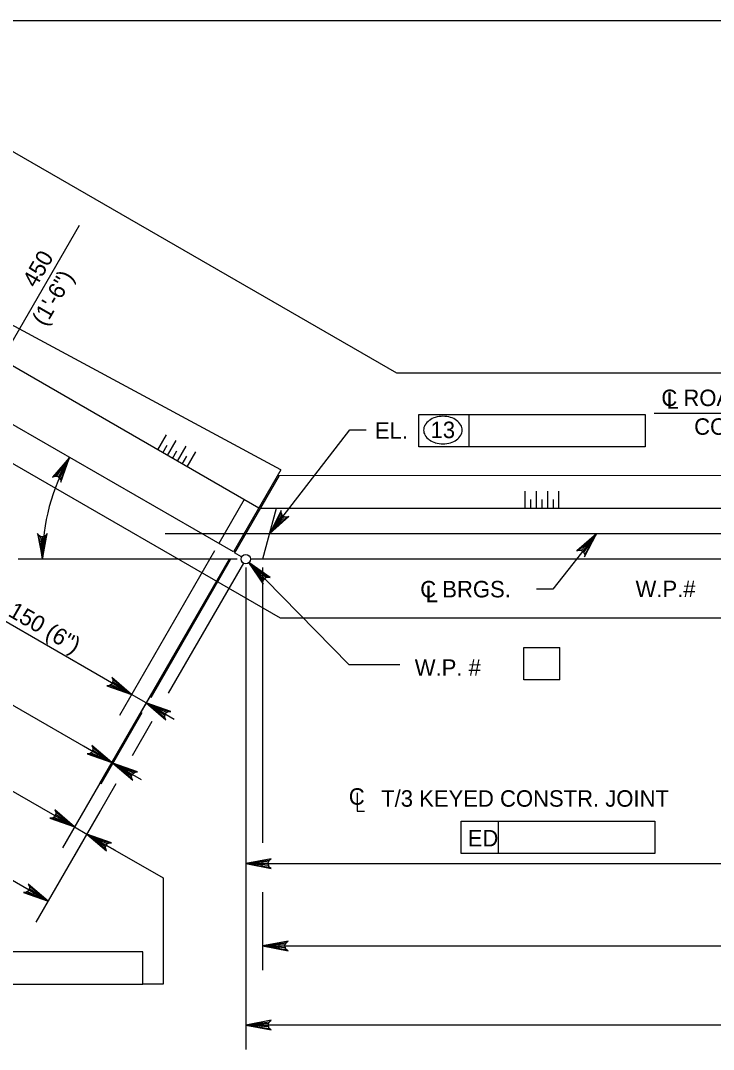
# Model space of a CAD drawing. Extents: x 638340 to 640241, y 295465 to 298435.
# Drawn here: x 638568.5 to 638694.6, y 297045.1 to 297232.5 of the extents above; entities that cross this region are included whole.
import ezdxf

# ---------------------------------------------------------------- set-up
doc = ezdxf.new("R2010")
doc.units = 0
for name, color, linetype in [('10', 7, 'Continuous'), ('2', 7, 'Continuous'), ('3', 7, 'Continuous')]:
    doc.layers.add(name, color=color, linetype=linetype)

msp = doc.modelspace()

# ---------------------------------------------------------------- linework, layer by layer
at = {"layer": '10'}
for p, q in [((638636.98, 297168.22), (638562.15, 297211.42)), ((638615.83, 297150.61), (638548.15, 297187.17)), ((638611.82, 297143.67), (638545.23, 297182.12)), ((638607.21, 297135.68), (638541.35, 297173.7)), ((638615.8, 297123.61), (638537.54, 297168.8)), ((638811.23, 297168.22), (638636.98, 297168.22)), ((638615.83, 297150.61), (638607.21, 297135.68)), ((638615.56, 297149.63), (638607.43, 297135.55)), ((638615.56, 297149.63), (638831.73, 297149.7)), ((638609.16, 297145.21), (638604.55, 297137.22)), ((638835.25, 297143.61), (638612.08, 297143.61)), ((638615.01, 297143.61), (638612.53, 297134.38)), ((638860.01, 297138.99), (638594.8, 297138.99)), ((638608.72, 297134.81), (638607.43, 297135.55)), ((638725.26, 297134.38), (638610.31, 297134.38)), ((638835.48, 297123.61), (638615.8, 297123.61))]:
    msp.add_line(p, q, dxfattribs=at)
at = {"layer": '2'}
for p, q in [((638475.46, 297232.46), (639261.46, 297232.46)), ((638593.47, 297154.26), (638595.05, 297157)), ((638594.36, 297153.75), (638595.17, 297155.16)), ((638595.25, 297153.24), (638596.83, 297155.98)), ((638597.02, 297152.21), (638598.6, 297154.95)), ((638596.13, 297152.73), (638596.95, 297154.13)), ((638597.91, 297151.7), (638598.72, 297153.11)), ((638598.8, 297151.19), (638600.38, 297153.93)), ((638660.33, 297143.61), (638660.33, 297146.77)), ((638661.36, 297143.61), (638661.36, 297145.23)), ((638662.38, 297143.61), (638662.38, 297146.77)), ((638663.41, 297143.61), (638663.41, 297145.23)), ((638664.43, 297143.61), (638664.43, 297146.77)), ((638665.46, 297143.61), (638665.46, 297145.23)), ((638666.48, 297143.61), (638666.48, 297146.77))]:
    msp.add_line(p, q, dxfattribs=at)
at = {"layer": '3'}
for p, q in [((638566.54, 297173.23), (638579.21, 297195.19)), ((638640.98, 297160.72), (638650.16, 297160.72)), ((638640.98, 297154.82), (638640.98, 297160.72)), ((638650.16, 297154.82), (638650.16, 297160.72)), ((638650.16, 297160.72), (638682.2, 297160.72)), ((638682.2, 297160.72), (638682.2, 297154.82)), ((638718.45, 297160.92), (638683.82, 297160.92)), ((638613.77, 297138.99), (638628.44, 297157.93)), ((638628.44, 297157.93), (638631.4, 297157.93)), ((638682.2, 297154.82), (638640.98, 297154.82)), ((638673.33, 297138.99), (638665.37, 297128.91)), ((638603.78, 297135.88), (638586.47, 297105.91)), ((638607.92, 297134.38), (638568.02, 297134.38)), ((638606.44, 297134.35), (638576.09, 297081.78)), ((638606.44, 297134.35), (638582.86, 297093.5)), ((638606.44, 297134.35), (638589.13, 297104.37)), ((638606.66, 297134.22), (638592.17, 297109.12)), ((638585.07, 297097.33), (638524.29, 297132.45)), ((638609.03, 297133.64), (638595.36, 297109.95)), ((638609.46, 297132.84), (638609.46, 297074.5)), ((638610.02, 297133.74), (638628.24, 297115.21)), ((638612.53, 297132.84), (638612.53, 297082.7)), ((638665.37, 297128.91), (638662.41, 297128.91)), ((638583.57, 297112.7), (638561.85, 297125.23)), ((638511.71, 297124.06), (638578.3, 297085.61)), ((638660.06, 297118.29), (638666.66, 297118.29)), ((638660.06, 297112.38), (638660.06, 297118.29)), ((638666.66, 297112.38), (638666.66, 297118.29)), ((638628.24, 297115.21), (638637.49, 297115.21)), ((638573.49, 297072.08), (638504.64, 297111.82)), ((638588.68, 297109.74), (638583.57, 297112.7)), ((638666.66, 297112.38), (638660.06, 297112.38)), ((638591.35, 297108.21), (638588.69, 297109.75)), ((638591.35, 297108.21), (638596.46, 297105.25)), ((638590.58, 297106.37), (638583.08, 297093.37)), ((638592.37, 297104.79), (638588.77, 297098.55)), ((638582.52, 297098.81), (638579.96, 297100.29)), ((638585.29, 297097.21), (638585.07, 297097.34)), ((638585.29, 297097.21), (638590.41, 297094.25)), ((638585.84, 297093.48), (638578.34, 297080.48)), ((638609.46, 297093.82), (638609.46, 297045.09)), ((638629.72, 297091.82), (638629.72, 297088.5)), ((638582.91, 297088.39), (638571.27, 297068.24)), ((638575.75, 297087.09), (638573.19, 297088.56)), ((638629.72, 297088.5), (638631.11, 297088.5)), ((638578.3, 297085.61), (638580.55, 297084.31)), ((638648.66, 297086.66), (638655.5, 297086.66)), ((638648.66, 297080.75), (638648.66, 297086.66)), ((638655.5, 297080.75), (638655.5, 297086.66)), ((638655.5, 297086.66), (638683.96, 297086.66)), ((638683.96, 297086.66), (638683.96, 297080.75)), ((638580.55, 297084.32), (638594.42, 297076.31)), ((638583.11, 297082.84), (638585.67, 297081.36)), ((638683.96, 297080.75), (638648.66, 297080.75)), ((638609.46, 297078.93), (638718.12, 297078.93)), ((638594.42, 297076.31), (638594.42, 297056.96)), ((638612.53, 297073.71), (638612.53, 297059.5)), ((638583.87, 297062.86), (638555.41, 297062.86)), ((638590.71, 297062.86), (638583.87, 297062.86)), ((638590.71, 297056.96), (638590.71, 297062.86)), ((638612.53, 297063.93), (638829.61, 297063.93)), ((638555.41, 297056.96), (638590.71, 297056.96)), ((638594.42, 297056.96), (638590.71, 297056.96)), ((638837.73, 297049.52), (638609.46, 297049.52))]:
    msp.add_line(p, q, dxfattribs=at)
for points in [[(638577.4, 297152.89), (638574.32, 297149.29), (638574.71, 297149.47), (638575.08, 297149.48), (638575.37, 297149.37), (638575.62, 297149.16), (638575.8, 297148.85), (638575.83, 297148.41), (638577.4, 297152.89), (638575.8, 297148.85), (638575.62, 297149.16), (638577.4, 297152.89), (638575.37, 297149.37), (638575.08, 297149.48), (638577.4, 297152.89), (638574.71, 297149.47)], [(638613.77, 297138.99), (638617.32, 297142.14), (638616.9, 297142.01), (638616.54, 297142.06), (638616.26, 297142.2), (638616.04, 297142.44), (638615.91, 297142.78), (638615.93, 297143.21), (638613.77, 297138.99), (638615.91, 297142.78), (638616.04, 297142.44), (638613.77, 297138.99), (638616.26, 297142.2), (638616.54, 297142.06), (638613.77, 297138.99), (638616.9, 297142.01)], [(638572.45, 297134.38), (638573.32, 297139.04), (638573.07, 297138.68), (638572.76, 297138.5), (638572.45, 297138.44), (638572.13, 297138.5), (638571.82, 297138.68), (638571.57, 297139.04), (638572.45, 297134.38), (638571.82, 297138.68), (638572.13, 297138.5), (638572.45, 297134.38), (638572.45, 297138.44), (638572.76, 297138.5), (638572.45, 297134.38), (638573.07, 297138.68)], [(638673.33, 297138.99), (638669.76, 297135.88), (638670.18, 297136.01), (638670.54, 297135.96), (638670.82, 297135.81), (638671.03, 297135.57), (638671.16, 297135.23), (638671.13, 297134.8), (638673.33, 297138.99), (638671.16, 297135.23), (638671.03, 297135.57), (638673.33, 297138.99), (638670.82, 297135.81), (638670.54, 297135.96), (638673.33, 297138.99), (638670.18, 297136.01)], [(638610.02, 297133.74), (638612.66, 297129.81), (638612.59, 297130.24), (638612.68, 297130.59), (638612.87, 297130.85), (638613.13, 297131.03), (638613.48, 297131.11), (638613.91, 297131.03), (638610.02, 297133.74), (638613.48, 297131.11), (638613.13, 297131.03), (638610.02, 297133.74), (638612.87, 297130.85), (638612.68, 297130.59), (638610.02, 297133.74), (638612.59, 297130.24)], [(638588.68, 297109.74), (638585.09, 297112.83), (638585.27, 297112.44), (638585.28, 297112.07), (638585.17, 297111.78), (638584.96, 297111.53), (638584.65, 297111.35), (638584.21, 297111.32), (638588.68, 297109.74), (638584.65, 297111.35), (638584.96, 297111.53), (638588.68, 297109.74), (638585.17, 297111.78), (638585.28, 297112.07), (638588.68, 297109.74), (638585.27, 297112.44)], [(638591.35, 297108.21), (638594.95, 297105.12), (638594.76, 297105.51), (638594.76, 297105.88), (638594.87, 297106.18), (638595.07, 297106.42), (638595.39, 297106.6), (638595.82, 297106.63), (638591.35, 297108.21), (638595.39, 297106.6), (638595.07, 297106.42), (638591.35, 297108.21), (638594.87, 297106.18), (638594.76, 297105.88), (638591.35, 297108.21), (638594.76, 297105.51)], [(638585.07, 297097.33), (638581.47, 297100.42), (638581.66, 297100.03), (638581.66, 297099.66), (638581.56, 297099.37), (638581.35, 297099.12), (638581.03, 297098.94), (638580.6, 297098.91), (638585.07, 297097.33), (638581.03, 297098.94), (638581.35, 297099.12), (638585.07, 297097.33), (638581.56, 297099.37), (638581.66, 297099.66), (638585.07, 297097.33), (638581.66, 297100.03)], [(638585.29, 297097.21), (638588.89, 297094.12), (638588.71, 297094.51), (638588.7, 297094.88), (638588.81, 297095.17), (638589.02, 297095.42), (638589.33, 297095.6), (638589.77, 297095.63), (638585.29, 297097.21), (638589.33, 297095.6), (638589.02, 297095.42), (638585.29, 297097.21), (638588.81, 297095.17), (638588.7, 297094.88), (638585.29, 297097.21), (638588.71, 297094.51)], [(638578.3, 297085.61), (638574.7, 297088.7), (638574.89, 297088.3), (638574.9, 297087.94), (638574.79, 297087.64), (638574.58, 297087.4), (638574.27, 297087.22), (638573.83, 297087.18), (638578.3, 297085.61), (638574.27, 297087.22), (638574.58, 297087.4), (638578.3, 297085.61), (638574.79, 297087.64), (638574.9, 297087.94), (638578.3, 297085.61), (638574.89, 297088.3)], [(638580.55, 297084.32), (638584.15, 297081.23), (638583.97, 297081.62), (638583.96, 297081.99), (638584.07, 297082.28), (638584.27, 297082.53), (638584.59, 297082.71), (638585.03, 297082.74), (638580.55, 297084.32), (638584.59, 297082.71), (638584.27, 297082.53), (638580.55, 297084.32), (638584.07, 297082.28), (638583.96, 297081.99), (638580.55, 297084.32), (638583.97, 297081.62)], [(638609.46, 297078.93), (638614.12, 297078.05), (638613.76, 297078.3), (638613.58, 297078.61), (638613.52, 297078.93), (638613.58, 297079.24), (638613.76, 297079.55), (638614.12, 297079.8), (638609.46, 297078.93), (638613.76, 297079.55), (638613.58, 297079.24), (638609.46, 297078.93), (638613.52, 297078.93), (638613.58, 297078.61), (638609.46, 297078.93), (638613.76, 297078.3)], [(638573.49, 297072.08), (638569.89, 297075.16), (638570.08, 297074.77), (638570.08, 297074.41), (638569.97, 297074.11), (638569.77, 297073.86), (638569.45, 297073.68), (638569.01, 297073.65), (638573.49, 297072.08), (638569.45, 297073.68), (638569.77, 297073.86), (638573.49, 297072.08), (638569.97, 297074.11), (638570.08, 297074.41), (638573.49, 297072.08), (638570.08, 297074.77)], [(638612.53, 297063.93), (638617.19, 297063.06), (638616.84, 297063.31), (638616.65, 297063.62), (638616.6, 297063.93), (638616.65, 297064.25), (638616.84, 297064.56), (638617.19, 297064.81), (638612.53, 297063.93), (638616.84, 297064.56), (638616.65, 297064.25), (638612.53, 297063.93), (638616.6, 297063.93), (638616.65, 297063.62), (638612.53, 297063.93), (638616.84, 297063.31)], [(638609.46, 297049.52), (638614.12, 297048.65), (638613.76, 297048.89), (638613.58, 297049.21), (638613.52, 297049.52), (638613.58, 297049.83), (638613.76, 297050.14), (638614.12, 297050.39), (638609.46, 297049.52), (638613.76, 297050.14), (638613.58, 297049.83), (638609.46, 297049.52), (638613.52, 297049.52), (638613.58, 297049.21), (638609.46, 297049.52), (638613.76, 297048.89)]]:
    msp.add_lwpolyline(points, dxfattribs=at)
for points in [[(638615.97, 297141.03), (638615.19, 297141.63), (638613.77, 297138.99)], [(638671.12, 297136.98), (638671.89, 297136.37), (638673.33, 297138.99)], [(638612.44, 297131.98), (638611.74, 297131.29), (638610.02, 297133.74)], [(638586.37, 297111.65), (638585.88, 297110.8), (638588.69, 297109.75)], [(638594.15, 297107.16), (638593.66, 297106.3), (638591.35, 297108.21)], [(638582.76, 297099.24), (638582.27, 297098.39), (638585.07, 297097.34)], [(638588.1, 297096.16), (638587.61, 297095.3), (638585.29, 297097.21)], [(638575.99, 297087.51), (638575.5, 297086.66), (638578.3, 297085.61)], [(638583.36, 297083.26), (638582.86, 297082.41), (638580.55, 297084.31)], [(638612.41, 297079.42), (638612.41, 297078.43), (638609.46, 297078.93)], [(638571.18, 297073.98), (638570.68, 297073.13), (638573.49, 297072.08)], [(638615.49, 297064.43), (638615.49, 297063.44), (638612.53, 297063.93)], [(638612.41, 297050.01), (638612.41, 297049.02), (638609.46, 297049.52)]]:
    msp.add_lwpolyline(points, close=True, dxfattribs=at)
msp.add_circle((638609.46, 297134.38), 0.85, dxfattribs=at)
for centre, radius, start, end in [((638645.02, 297156.68), 3.66, 106.5358, 125.6316), ((638645.36, 297155.52), 4.87, 90, 106.5358), ((638645.36, 297155.52), 4.87, 73.4642, 90), ((638645.71, 297156.68), 3.66, 54.3684, 73.4642), ((638643.68, 297157.88), 1.83, 149.9767, 180), ((638644.49, 297157.41), 2.76, 125.6316, 149.9767), ((638646.23, 297157.41), 2.76, 30.0233, 54.3684), ((638647.04, 297157.88), 1.83, 0, 30.0233), ((638643.68, 297157.88), 1.83, 180, 210.0233), ((638644.49, 297158.34), 2.76, 210.0233, 234.3684), ((638646.23, 297158.34), 2.76, 305.6316, 329.9767), ((638647.04, 297157.88), 1.83, 329.9767, 0), ((638645.02, 297159.08), 3.66, 234.3684, 253.4642), ((638645.36, 297160.24), 4.87, 253.4642, 270), ((638645.36, 297160.24), 4.87, 270, 286.5358), ((638645.71, 297159.08), 3.66, 286.5358, 305.6316), ((638609.46, 297134.38), 37.01, 149.9994, 179.9989)]:
    msp.add_arc(centre, radius, start, end, dxfattribs=at)

# ---------------------------------------------------------------- texts
for s, rotation, p in [('450', 60, (638571.25, 297183.63)), ('(1\'-6")', 60, (638572.98, 297176.62)), ('150 (6")', 330, (638566.02, 297124.14))]:
    msp.add_text(s, height=3, rotation=rotation, dxfattribs=at).set_placement(p)
for s, height, p in [('C ROADWAY &', 3.0001, (638685.12, 297162.25)), ('L', 3, (638686.08, 297161.76)), ('EL.', 3, (638632.97, 297156.3)), ('13', 3, (638643.11, 297156.42)), ('CONSTR. B', 3, (638691.09, 297157.02)), ('C BRGS.', 3, (638641.23, 297127.41)), ('W.P.#', 3, (638680.42, 297127.46)), ('L', 3, (638642.22, 297126.53)), ('W.P. #', 3, (638640.23, 297113.13)), ('C', 3, (638628.22, 297089.65)), ('T/3 KEYED CONSTR. JOINT', 3.0001, (638634.12, 297089.29)), ('ED', 3, (638649.87, 297082.06))]:
    msp.add_text(s, height=height, dxfattribs=at).set_placement(p)

doc.saveas('drawing.dxf')
